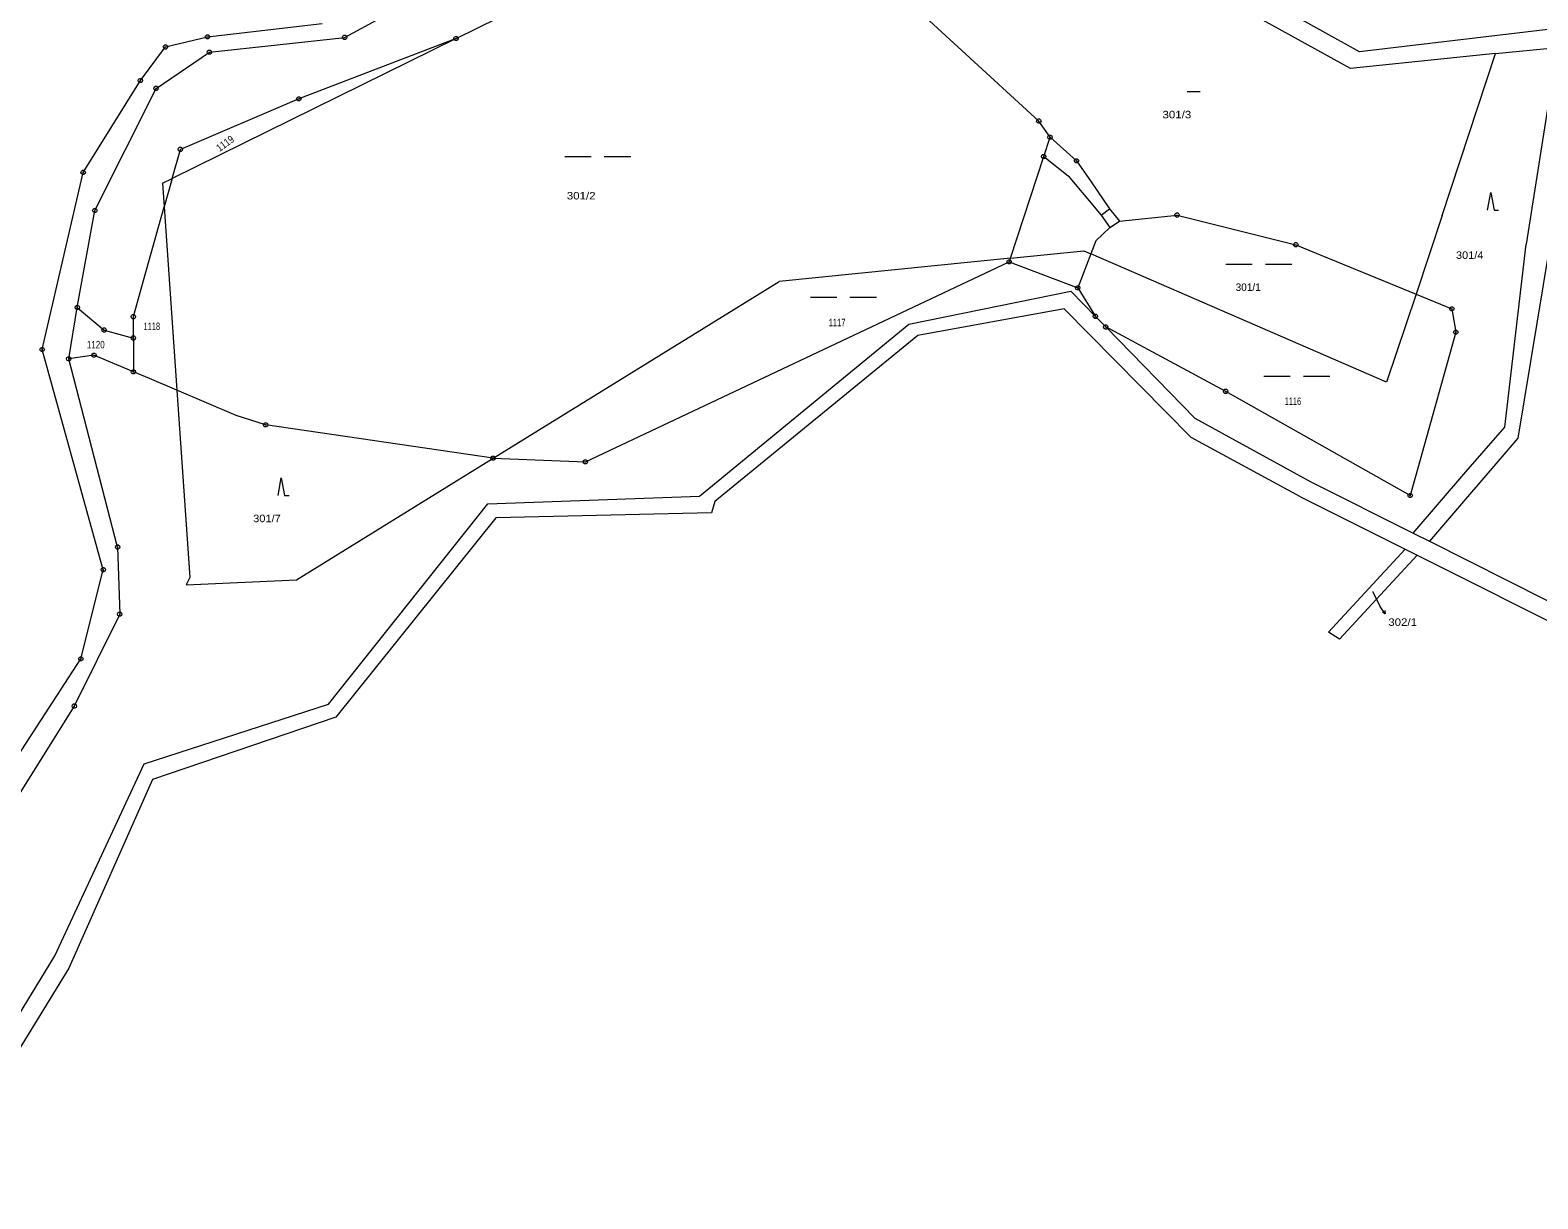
# Model space of a CAD drawing. Extents: x -687390 to -684106, y -954833 to -951648.
# Drawn here: x -685024.6 to -684682, y -953163 to -952897.4 of the extents above; entities that cross this region are included whole.
import ezdxf

# ---------------------------------------------------------------- set-up
doc = ezdxf.new("R2010")
doc.units = 0
doc.header["$LTSCALE"] = 0.68
for name, color, linetype, lineweight in [('1', 7, 'Continuous', 13), ('3', 7, 'Continuous', 13), ('4', 7, 'Continuous', 13), ('7', 7, 'Continuous', 13), ('8', 7, 'Continuous', 13)]:
    doc.layers.add(name, color=color, linetype=linetype, lineweight=lineweight)
doc.layers.add('2', color=7, linetype='Continuous')

msp = doc.modelspace()

# ---------------------------------------------------------------- linework, layer by layer
at = {"layer": '1'}
for p, q in [((-684927.83, -952899.31), (-684894.83, -952883.03)), ((-684927.83, -952899.31), (-684992.37, -952931.14)), ((-684992.37, -952931.14), (-684990.5, -952924.51)), ((-684994.54, -952932.21), (-684992.37, -952931.14)), ((-684994.54, -952932.21), (-684994.17, -952937.56)), ((-684998.86, -952954.29), (-684994.17, -952937.56)), ((-684994.17, -952937.56), (-684991.27, -952979.26)), ((-684763.99, -952939.43), (-684737, -952946.19)), ((-684703.71, -952939.53), (-684709.68, -952957.4)), ((-684801.88, -952949.23), (-684785.14, -952947.54)), ((-684785.14, -952947.54), (-684783.6, -952948.22)), ((-684689.53, -952987.61), (-684684.67, -952946.04)), ((-684801.88, -952949.23), (-684854.41, -952954.55)), ((-684801.88, -952949.23), (-684802.15, -952950.06)), ((-684716.37, -952977.44), (-684783.6, -952948.22)), ((-684919.44, -952994.72), (-684854.41, -952954.55)), ((-684709.68, -952957.4), (-684716.37, -952977.44)), ((-685008.02, -953020.04), (-685021.9, -952969.99)), ((-685004.75, -953014.9), (-685015.85, -952972.14)), ((-684991.27, -952979.26), (-684988.32, -953021.82)), ((-684964.08, -953022.32), (-684919.44, -952994.72)), ((-684735.94, -953003.48), (-684712.14, -953015.39)), ((-684712.14, -953015.39), (-684729.56, -953034.2)), ((-684709.43, -953016.75), (-684727.1, -953035.82)), ((-684727.1, -953035.82), (-684729.56, -953034.2))]:
    msp.add_line(p, q, dxfattribs=at)
for points in [[(-684572.19, -952741.46), (-684577.57, -952740.32), (-684596.84, -952808.54), (-684634.89, -952835.88), (-684674.58, -952896.63), (-684722.51, -952902.33), (-684776.6, -952872.26)], [(-684900.57, -952865.06), (-684913.45, -952877.51), (-684953.15, -952899.05)], [(-684894.83, -952883.03), (-684846.02, -952871.61), (-684795.41, -952918.08)], [(-684691.61, -952902.74), (-684724.57, -952906.15), (-684774.06, -952878.76)], [(-684999.58, -952908.86), (-684993.86, -952901.24), (-684984.33, -952898.96), (-684958.25, -952895.89)], [(-684996.01, -952910.64), (-684983.91, -952902.43), (-684953.15, -952899.05)], [(-684927.83, -952899.31), (-684963.57, -952913.05), (-684990.5, -952924.51)], [(-684671.85, -952900.02), (-684679.33, -952946.56), (-684686.52, -952990.13), (-684706.64, -953013.58), (-684671.14, -953031.43)], [(-684703.71, -952939.53), (-684691.61, -952902.74), (-684677.64, -952901.32), (-684684.67, -952946.04)], [(-685021.9, -952969.99), (-685012.59, -952929.74), (-684999.58, -952908.86)], [(-685013.93, -952960.47), (-685009.92, -952938.43), (-684996.01, -952910.64)], [(-684801.88, -952949.23), (-684794.3, -952926.16), (-684792.85, -952921.75), (-684795.41, -952918.08)], [(-684792.85, -952921.75), (-684786.84, -952927.12), (-684783.53, -952931.9), (-684779.31, -952937.99), (-684777.1, -952940.8), (-684763.99, -952939.43)], [(-684737, -952946.19), (-684709.68, -952957.4), (-684701.55, -952960.74), (-684700.64, -952966.05), (-684708.74, -952995.04), (-684711.01, -953003.19), (-684752.94, -952979.51), (-684780.19, -952964.88)], [(-684919.44, -952994.72), (-684898.46, -952995.53), (-684802.15, -952950.06)], [(-684802.15, -952950.06), (-684786.55, -952955.97), (-684782.55, -952962.47)], [(-685001.18, -952967.39), (-685001.18, -952962.53), (-684998.86, -952954.29)], [(-685153.6, -953200.94), (-685122.18, -953199.86), (-685080.85, -953187.35), (-685050.24, -953158.94), (-685018.99, -953107.8), (-684998.75, -953064.19), (-684956.81, -953050.62), (-684920.62, -953005.09), (-684872.51, -953003.35), (-684824.97, -952964.25), (-684788.15, -952956.74)], [(-684780.19, -952964.88), (-684782.55, -952962.47), (-684788.15, -952956.74)], [(-684735.94, -953003.48), (-684760.81, -952990), (-684789.64, -952960.77), (-684822.87, -952966.79), (-684869.05, -953004.54), (-684869.76, -953007.13), (-684918.82, -953008.26), (-684955.2, -953053.57), (-684996.85, -953067.73), (-685015.85, -953110.63), (-685047.36, -953161.86), (-685081.76, -953191.92), (-685120.68, -953204.01), (-685154.57, -953205.82)], [(-684977.82, -952984.97), (-684991.27, -952979.26), (-684997.51, -952976.62), (-685001.17, -952975.07), (-685010.13, -952971.27), (-685015.85, -952972.14), (-685013.93, -952960.47), (-685007.83, -952965.57), (-685001.18, -952967.39), (-685001.17, -952975.07)], [(-684780.19, -952964.88), (-684759.92, -952985.6), (-684733.56, -953000.05)], [(-684919.44, -952994.72), (-684971.12, -952987.12), (-684977.82, -952984.97)], [(-684710.37, -953011.71), (-684698.36, -952997.82), (-684689.53, -952987.61)], [(-684733.56, -953000.05), (-684710.37, -953011.71), (-684706.64, -953013.58)], [(-685004.75, -953014.9), (-685004.28, -953030.16), (-685014.6, -953051.04), (-685037.2, -953087.07)], [(-684712.14, -953015.39), (-684709.43, -953016.75), (-684672.05, -953035.46)], [(-685043.77, -953087.52), (-685013.12, -953040.29), (-685008.02, -953020.04)], [(-684988.32, -953021.82), (-684989.17, -953023.5), (-684964.08, -953022.32)]]:
    msp.add_lwpolyline(points, dxfattribs=at)
at = {"layer": '3'}
for p, q in [((-684761.71, -952911.37), (-684758.71, -952911.37)), ((-684903.15, -952926.1), (-684897.15, -952926.1)), ((-684894.15, -952926.1), (-684888.15, -952926.1)), ((-684752.91, -952950.63), (-684746.91, -952950.63)), ((-684743.91, -952950.63), (-684737.91, -952950.63)), ((-684847.33, -952958.07), (-684841.33, -952958.07)), ((-684838.33, -952958.07), (-684832.33, -952958.07)), ((-684744.27, -952976.03), (-684738.27, -952976.03)), ((-684735.27, -952976.03), (-684729.27, -952976.03))]:
    msp.add_line(p, q, dxfattribs=at)
for points in [[(-684693.45, -952938.34), (-684692.7, -952934.34), (-684691.95, -952938.34), (-684690.95, -952938.34)], [(-684968.3, -953003.16), (-684967.55, -952999.16), (-684966.8, -953003.16), (-684965.8, -953003.16)]]:
    msp.add_lwpolyline(points, dxfattribs=at)
at = {"layer": '4'}
for p, q in [((-684992.37, -952931.14), (-684994.17, -952937.56)), ((-684781.26, -952939.45), (-684779.31, -952937.99)), ((-684779.25, -952942.23), (-684777.1, -952940.8)), ((-684783.6, -952948.22), (-684786.55, -952955.97))]:
    msp.add_line(p, q, dxfattribs=at)
msp.add_lwpolyline([(-684794.3, -952926.16), (-684788.7, -952930.51), (-684783.97, -952936.18), (-684781.26, -952939.45), (-684779.25, -952942.23), (-684782.47, -952945.26), (-684783.6, -952948.22)], dxfattribs=at)
at = {"layer": '7'}
for p in [(-684719.6, -953024.99), (-684716.681, -953030.072)]:
    msp.add_line(p, (-684717.84, -953028.43), dxfattribs=at)
msp.add_lwpolyline([(-684716.794, -953029.332), (-684716.681, -953030.072), (-684717.341, -953029.718)], dxfattribs=at)
at = {"layer": '8'}
for p, q in [((-684984.45, -952898.96), (-684984.21, -952898.96)), ((-684953.27, -952899.05), (-684953.03, -952899.05)), ((-684927.95, -952899.31), (-684927.71, -952899.31)), ((-684993.98, -952901.24), (-684993.74, -952901.24)), ((-684984.03, -952902.43), (-684983.79, -952902.43)), ((-684999.7, -952908.86), (-684999.46, -952908.86)), ((-684996.13, -952910.64), (-684995.89, -952910.64)), ((-684963.69, -952913.05), (-684963.45, -952913.05)), ((-684795.53, -952918.08), (-684795.29, -952918.08)), ((-684792.97, -952921.75), (-684792.73, -952921.75)), ((-684990.62, -952924.51), (-684990.38, -952924.51)), ((-684794.42, -952926.16), (-684794.18, -952926.16)), ((-684786.96, -952927.12), (-684786.72, -952927.12)), ((-685012.71, -952929.74), (-685012.47, -952929.74)), ((-685010.04, -952938.43), (-685009.8, -952938.43)), ((-684764.11, -952939.43), (-684763.87, -952939.43)), ((-684737.12, -952946.19), (-684736.88, -952946.19)), ((-684802.27, -952950.06), (-684802.03, -952950.06)), ((-684786.67, -952955.97), (-684786.43, -952955.97)), ((-685014.05, -952960.47), (-685013.81, -952960.47)), ((-684701.67, -952960.74), (-684701.43, -952960.74)), ((-685001.3, -952962.53), (-685001.06, -952962.53)), ((-684782.67, -952962.47), (-684782.43, -952962.47)), ((-684780.31, -952964.88), (-684780.07, -952964.88)), ((-685007.95, -952965.57), (-685007.71, -952965.57)), ((-685001.3, -952967.39), (-685001.06, -952967.39)), ((-684700.76, -952966.05), (-684700.52, -952966.05)), ((-685022.02, -952969.99), (-685021.78, -952969.99)), ((-685010.25, -952971.27), (-685010.01, -952971.27)), ((-685015.97, -952972.14), (-685015.73, -952972.14)), ((-685001.29, -952975.07), (-685001.05, -952975.07)), ((-684753.06, -952979.51), (-684752.82, -952979.51)), ((-684971.24, -952987.12), (-684971, -952987.12)), ((-684919.56, -952994.72), (-684919.32, -952994.72)), ((-684898.58, -952995.53), (-684898.34, -952995.53)), ((-684711.13, -953003.19), (-684710.89, -953003.19)), ((-685004.87, -953014.9), (-685004.63, -953014.9)), ((-685008.14, -953020.04), (-685007.9, -953020.04)), ((-685004.4, -953030.16), (-685004.16, -953030.16)), ((-685013.24, -953040.29), (-685013, -953040.29)), ((-685014.72, -953051.04), (-685014.48, -953051.04))]:
    msp.add_line(p, q, dxfattribs=at)
for points in [[(-684984.18, -952898.48), (-684983.93, -952898.66), (-684983.83, -952898.95), (-684983.93, -952899.24), (-684984.18, -952899.42), (-684984.49, -952899.42), (-684984.74, -952899.24), (-684984.84, -952898.95), (-684984.74, -952898.66), (-684984.49, -952898.48)], [(-684953, -952898.57), (-684952.75, -952898.75), (-684952.65, -952899.04), (-684952.75, -952899.33), (-684953, -952899.51), (-684953.31, -952899.51), (-684953.56, -952899.33), (-684953.66, -952899.04), (-684953.56, -952898.75), (-684953.31, -952898.57)], [(-684927.68, -952898.83), (-684927.43, -952899.01), (-684927.33, -952899.3), (-684927.43, -952899.59), (-684927.68, -952899.77), (-684927.99, -952899.77), (-684928.24, -952899.59), (-684928.34, -952899.3), (-684928.24, -952899.01), (-684927.99, -952898.83)], [(-684993.71, -952900.76), (-684993.46, -952900.94), (-684993.36, -952901.23), (-684993.46, -952901.52), (-684993.71, -952901.7), (-684994.02, -952901.7), (-684994.27, -952901.52), (-684994.37, -952901.23), (-684994.27, -952900.94), (-684994.02, -952900.76)], [(-684983.76, -952901.95), (-684983.51, -952902.13), (-684983.41, -952902.42), (-684983.51, -952902.71), (-684983.76, -952902.89), (-684984.07, -952902.89), (-684984.32, -952902.71), (-684984.42, -952902.42), (-684984.32, -952902.13), (-684984.07, -952901.95)], [(-684999.43, -952908.38), (-684999.18, -952908.56), (-684999.08, -952908.85), (-684999.18, -952909.14), (-684999.43, -952909.32), (-684999.74, -952909.32), (-684999.99, -952909.14), (-685000.09, -952908.85), (-684999.99, -952908.56), (-684999.74, -952908.38)], [(-684995.86, -952910.16), (-684995.61, -952910.34), (-684995.51, -952910.63), (-684995.61, -952910.92), (-684995.86, -952911.1), (-684996.17, -952911.1), (-684996.42, -952910.92), (-684996.52, -952910.63), (-684996.42, -952910.34), (-684996.17, -952910.16)], [(-684963.42, -952912.57), (-684963.17, -952912.75), (-684963.07, -952913.04), (-684963.17, -952913.33), (-684963.42, -952913.51), (-684963.73, -952913.51), (-684963.98, -952913.33), (-684964.08, -952913.04), (-684963.98, -952912.75), (-684963.73, -952912.57)], [(-684795.26, -952917.6), (-684795.01, -952917.78), (-684794.91, -952918.07), (-684795.01, -952918.36), (-684795.26, -952918.54), (-684795.57, -952918.54), (-684795.82, -952918.36), (-684795.92, -952918.07), (-684795.82, -952917.78), (-684795.57, -952917.6)], [(-684792.7, -952921.27), (-684792.45, -952921.45), (-684792.35, -952921.74), (-684792.45, -952922.03), (-684792.7, -952922.21), (-684793.01, -952922.21), (-684793.26, -952922.03), (-684793.36, -952921.74), (-684793.26, -952921.45), (-684793.01, -952921.27)], [(-684990.35, -952924.03), (-684990.1, -952924.21), (-684990, -952924.5), (-684990.1, -952924.79), (-684990.35, -952924.97), (-684990.66, -952924.97), (-684990.91, -952924.79), (-684991.01, -952924.5), (-684990.91, -952924.21), (-684990.66, -952924.03)], [(-684794.15, -952925.68), (-684793.9, -952925.86), (-684793.8, -952926.15), (-684793.9, -952926.44), (-684794.15, -952926.62), (-684794.46, -952926.62), (-684794.71, -952926.44), (-684794.81, -952926.15), (-684794.71, -952925.86), (-684794.46, -952925.68)], [(-684786.69, -952926.64), (-684786.44, -952926.82), (-684786.34, -952927.11), (-684786.44, -952927.4), (-684786.69, -952927.58), (-684787, -952927.58), (-684787.25, -952927.4), (-684787.35, -952927.11), (-684787.25, -952926.82), (-684787, -952926.64)], [(-685012.44, -952929.26), (-685012.19, -952929.44), (-685012.09, -952929.73), (-685012.19, -952930.02), (-685012.44, -952930.2), (-685012.75, -952930.2), (-685013, -952930.02), (-685013.1, -952929.73), (-685013, -952929.44), (-685012.75, -952929.26)], [(-685009.77, -952937.95), (-685009.52, -952938.13), (-685009.42, -952938.42), (-685009.52, -952938.71), (-685009.77, -952938.89), (-685010.08, -952938.89), (-685010.33, -952938.71), (-685010.43, -952938.42), (-685010.33, -952938.13), (-685010.08, -952937.95)], [(-684763.84, -952938.95), (-684763.59, -952939.13), (-684763.49, -952939.42), (-684763.59, -952939.71), (-684763.84, -952939.89), (-684764.15, -952939.89), (-684764.4, -952939.71), (-684764.5, -952939.42), (-684764.4, -952939.13), (-684764.15, -952938.95)], [(-684736.85, -952945.71), (-684736.6, -952945.89), (-684736.5, -952946.18), (-684736.6, -952946.47), (-684736.85, -952946.65), (-684737.16, -952946.65), (-684737.41, -952946.47), (-684737.51, -952946.18), (-684737.41, -952945.89), (-684737.16, -952945.71)], [(-684802, -952949.58), (-684801.75, -952949.76), (-684801.65, -952950.05), (-684801.75, -952950.34), (-684802, -952950.52), (-684802.31, -952950.52), (-684802.56, -952950.34), (-684802.66, -952950.05), (-684802.56, -952949.76), (-684802.31, -952949.58)], [(-684786.4, -952955.49), (-684786.15, -952955.67), (-684786.05, -952955.96), (-684786.15, -952956.25), (-684786.4, -952956.43), (-684786.71, -952956.43), (-684786.96, -952956.25), (-684787.06, -952955.96), (-684786.96, -952955.67), (-684786.71, -952955.49)], [(-685013.78, -952959.99), (-685013.53, -952960.17), (-685013.43, -952960.46), (-685013.53, -952960.75), (-685013.78, -952960.93), (-685014.09, -952960.93), (-685014.34, -952960.75), (-685014.44, -952960.46), (-685014.34, -952960.17), (-685014.09, -952959.99)], [(-684701.4, -952960.26), (-684701.15, -952960.44), (-684701.05, -952960.73), (-684701.15, -952961.02), (-684701.4, -952961.2), (-684701.71, -952961.2), (-684701.96, -952961.02), (-684702.06, -952960.73), (-684701.96, -952960.44), (-684701.71, -952960.26)], [(-685001.03, -952962.05), (-685000.78, -952962.23), (-685000.68, -952962.52), (-685000.78, -952962.81), (-685001.03, -952962.99), (-685001.34, -952962.99), (-685001.59, -952962.81), (-685001.69, -952962.52), (-685001.59, -952962.23), (-685001.34, -952962.05)], [(-684782.4, -952961.99), (-684782.15, -952962.17), (-684782.05, -952962.46), (-684782.15, -952962.75), (-684782.4, -952962.93), (-684782.71, -952962.93), (-684782.96, -952962.75), (-684783.06, -952962.46), (-684782.96, -952962.17), (-684782.71, -952961.99)], [(-684780.04, -952964.4), (-684779.79, -952964.58), (-684779.69, -952964.87), (-684779.79, -952965.16), (-684780.04, -952965.34), (-684780.35, -952965.34), (-684780.6, -952965.16), (-684780.7, -952964.87), (-684780.6, -952964.58), (-684780.35, -952964.4)], [(-685007.68, -952965.09), (-685007.43, -952965.27), (-685007.33, -952965.56), (-685007.43, -952965.85), (-685007.68, -952966.03), (-685007.99, -952966.03), (-685008.24, -952965.85), (-685008.34, -952965.56), (-685008.24, -952965.27), (-685007.99, -952965.09)], [(-685001.03, -952966.91), (-685000.78, -952967.09), (-685000.68, -952967.38), (-685000.78, -952967.67), (-685001.03, -952967.85), (-685001.34, -952967.85), (-685001.59, -952967.67), (-685001.69, -952967.38), (-685001.59, -952967.09), (-685001.34, -952966.91)], [(-684700.49, -952965.57), (-684700.24, -952965.75), (-684700.14, -952966.04), (-684700.24, -952966.33), (-684700.49, -952966.51), (-684700.8, -952966.51), (-684701.05, -952966.33), (-684701.15, -952966.04), (-684701.05, -952965.75), (-684700.8, -952965.57)], [(-685021.75, -952969.51), (-685021.5, -952969.69), (-685021.4, -952969.98), (-685021.5, -952970.27), (-685021.75, -952970.45), (-685022.06, -952970.45), (-685022.31, -952970.27), (-685022.41, -952969.98), (-685022.31, -952969.69), (-685022.06, -952969.51)], [(-685015.7, -952971.66), (-685015.45, -952971.84), (-685015.35, -952972.13), (-685015.45, -952972.42), (-685015.7, -952972.6), (-685016.01, -952972.6), (-685016.26, -952972.42), (-685016.36, -952972.13), (-685016.26, -952971.84), (-685016.01, -952971.66)], [(-685009.98, -952970.79), (-685009.73, -952970.97), (-685009.63, -952971.26), (-685009.73, -952971.55), (-685009.98, -952971.73), (-685010.29, -952971.73), (-685010.54, -952971.55), (-685010.64, -952971.26), (-685010.54, -952970.97), (-685010.29, -952970.79)], [(-685001.02, -952974.59), (-685000.77, -952974.77), (-685000.67, -952975.06), (-685000.77, -952975.35), (-685001.02, -952975.53), (-685001.33, -952975.53), (-685001.58, -952975.35), (-685001.68, -952975.06), (-685001.58, -952974.77), (-685001.33, -952974.59)], [(-684752.79, -952979.03), (-684752.54, -952979.21), (-684752.44, -952979.5), (-684752.54, -952979.79), (-684752.79, -952979.97), (-684753.1, -952979.97), (-684753.35, -952979.79), (-684753.45, -952979.5), (-684753.35, -952979.21), (-684753.1, -952979.03)], [(-684970.97, -952986.64), (-684970.72, -952986.82), (-684970.62, -952987.11), (-684970.72, -952987.4), (-684970.97, -952987.58), (-684971.28, -952987.58), (-684971.53, -952987.4), (-684971.63, -952987.11), (-684971.53, -952986.82), (-684971.28, -952986.64)], [(-684919.29, -952994.24), (-684919.04, -952994.42), (-684918.94, -952994.71), (-684919.04, -952995), (-684919.29, -952995.18), (-684919.6, -952995.18), (-684919.85, -952995), (-684919.95, -952994.71), (-684919.85, -952994.42), (-684919.6, -952994.24)], [(-684898.31, -952995.05), (-684898.06, -952995.23), (-684897.96, -952995.52), (-684898.06, -952995.81), (-684898.31, -952995.99), (-684898.62, -952995.99), (-684898.87, -952995.81), (-684898.97, -952995.52), (-684898.87, -952995.23), (-684898.62, -952995.05)], [(-684710.86, -953002.71), (-684710.61, -953002.89), (-684710.51, -953003.18), (-684710.61, -953003.47), (-684710.86, -953003.65), (-684711.17, -953003.65), (-684711.42, -953003.47), (-684711.52, -953003.18), (-684711.42, -953002.89), (-684711.17, -953002.71)], [(-685004.6, -953014.42), (-685004.35, -953014.6), (-685004.25, -953014.89), (-685004.35, -953015.18), (-685004.6, -953015.36), (-685004.91, -953015.36), (-685005.16, -953015.18), (-685005.26, -953014.89), (-685005.16, -953014.6), (-685004.91, -953014.42)], [(-685007.87, -953019.56), (-685007.62, -953019.74), (-685007.52, -953020.03), (-685007.62, -953020.32), (-685007.87, -953020.5), (-685008.18, -953020.5), (-685008.43, -953020.32), (-685008.53, -953020.03), (-685008.43, -953019.74), (-685008.18, -953019.56)], [(-685004.13, -953029.68), (-685003.88, -953029.86), (-685003.78, -953030.15), (-685003.88, -953030.44), (-685004.13, -953030.62), (-685004.44, -953030.62), (-685004.69, -953030.44), (-685004.79, -953030.15), (-685004.69, -953029.86), (-685004.44, -953029.68)], [(-685012.97, -953039.81), (-685012.72, -953039.99), (-685012.62, -953040.28), (-685012.72, -953040.57), (-685012.97, -953040.75), (-685013.28, -953040.75), (-685013.53, -953040.57), (-685013.63, -953040.28), (-685013.53, -953039.99), (-685013.28, -953039.81)], [(-685014.45, -953050.56), (-685014.2, -953050.74), (-685014.1, -953051.03), (-685014.2, -953051.32), (-685014.45, -953051.5), (-685014.76, -953051.5), (-685015.01, -953051.32), (-685015.11, -953051.03), (-685015.01, -953050.74), (-685014.76, -953050.56)]]:
    msp.add_lwpolyline(points, close=True, dxfattribs=at)

# ---------------------------------------------------------------- texts
at = {"layer": '2'}
for s, height, width, p in [('301/3', 1.7, 1.15, (-684767.305, -952917.45)), ('301/2', 1.7, 1.15, (-684902.675, -952935.89)), ('301/4', 1.7, 1.1, (-684700.615, -952949.4)), ('1118', 1.7, 0.65, (-684998.855, -952965.57)), ('1117', 1.7, 0.6, (-684843.145, -952964.71)), ('1120', 1.7, 0.8, (-685011.745, -952969.74)), ('1116', 1.7, 0.65, (-684739.535, -952982.6)), ('301/7', 1.7, 1.1, (-684973.945, -953009.24)), ('302/1', 0.1, 1.15, (-684719.572, -953024.99))]:
    msp.add_text(s, height=height, dxfattribs=dict(at, width=width)).set_placement(p)
at = {"layer": '2', "width": 0.85}
msp.add_text('1119', height=1.7, rotation=35.867, dxfattribs=at).set_placement((-684981.574, -952925.11))
at = {"layer": '2'}
msp.add_text('301/1', height=1.7, dxfattribs=at).set_placement((-684750.675, -952956.68))
at = {"layer": '7', "width": 1.15}
msp.add_text('302/1', height=1.7, dxfattribs=at).set_placement((-684715.995, -953032.8))

doc.saveas('drawing.dxf')
